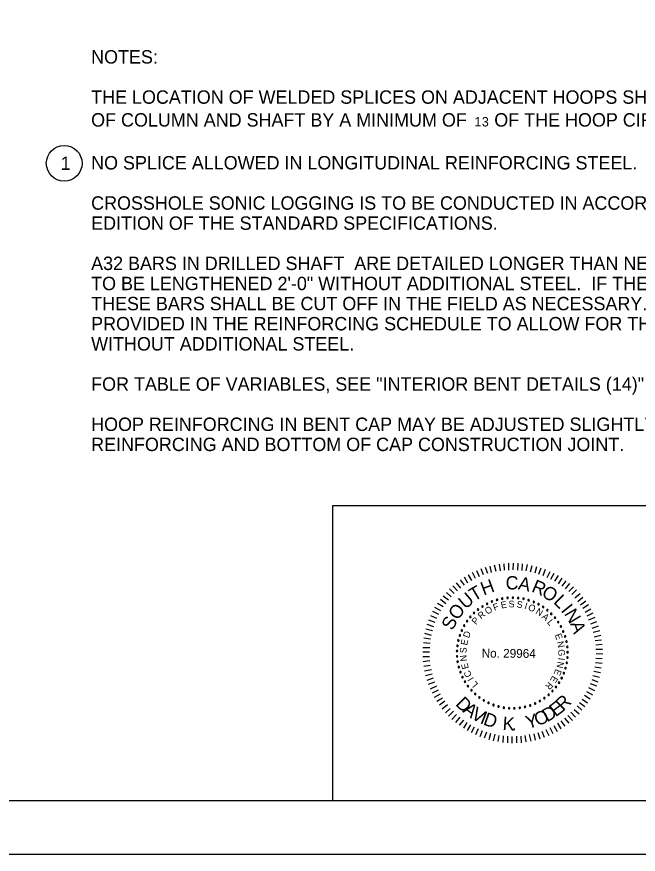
# Model space of a CAD drawing. Extents: x -225.1 to -152.9, y -16.8 to 27.2.
# Drawn here: x -185.7 to -174.12, y -16.78 to -1.16 of the extents above; entities that cross this region are included whole.
import ezdxf

# ---------------------------------------------------------------- set-up
doc = ezdxf.new("R2010")
doc.units = 0
for name, color, linetype in [('BR_AUTO DIMENSION', 7, 'Continuous'), ('BR_BORDER LINES', 7, 'Continuous'), ('BR_TEXT', 7, 'Continuous'), ('Level 31', 7, 'Continuous')]:
    doc.layers.add(name, color=color, linetype=linetype)

msp = doc.modelspace()

# ---------------------------------------------------------------- linework, layer by layer
at = {"layer": 'BR_AUTO DIMENSION'}
msp.add_circle((-184.815, -3.895), 0.333, dxfattribs=at)
at = {"layer": 'BR_BORDER LINES'}
for p, q in [((-179.809, -10.276), (-169.079, -10.276)), ((-179.809, -15.776), (-179.809, -10.276)), ((-221.411, -15.776), (-154.078, -15.776))]:
    msp.add_line(p, q, dxfattribs=at)
at = {"layer": 'BR_TEXT'}
for p, q in [((-176.765, -11.505), (-176.793, -11.386)), ((-176.686, -11.49), (-176.704, -11.368)), ((-176.607, -11.482), (-176.615, -11.36)), ((-176.528, -11.477), (-176.527, -11.349)), ((-176.444, -11.473), (-176.443, -11.349)), ((-176.36, -11.479), (-176.355, -11.35)), ((-176.279, -11.485), (-176.27, -11.363)), ((-176.202, -11.494), (-176.18, -11.372)), ((-176.121, -11.51), (-176.093, -11.392)), ((-177.151, -11.637), (-177.203, -11.525)), ((-177.077, -11.603), (-177.124, -11.491)), ((-176.999, -11.57), (-177.041, -11.453)), ((-176.92, -11.545), (-176.964, -11.429)), ((-176.848, -11.525), (-176.874, -11.403)), ((-176.039, -11.531), (-176.007, -11.41)), ((-175.966, -11.552), (-175.922, -11.438)), ((-175.887, -11.579), (-175.843, -11.463)), ((-175.815, -11.614), (-175.759, -11.503)), ((-175.743, -11.649), (-175.681, -11.538)), ((-177.352, -11.762), (-177.431, -11.661)), ((-177.29, -11.72), (-177.351, -11.611)), ((-177.22, -11.673), (-177.28, -11.564)), ((-175.668, -11.685), (-175.604, -11.578)), ((-175.602, -11.734), (-175.534, -11.626)), ((-175.535, -11.777), (-175.462, -11.677)), ((-177.544, -11.917), (-177.633, -11.829)), ((-177.486, -11.863), (-177.569, -11.773)), ((-177.42, -11.813), (-177.5, -11.713)), ((-175.47, -11.829), (-175.389, -11.731)), ((-175.407, -11.88), (-175.321, -11.791)), ((-175.351, -11.935), (-175.264, -11.848)), ((-177.653, -12.041), (-177.752, -11.963)), ((-177.603, -11.978), (-177.69, -11.894)), ((-175.295, -11.997), (-175.2, -11.914)), ((-175.24, -12.061), (-175.147, -11.985)), ((-177.798, -12.239), (-177.905, -12.175)), ((-177.749, -12.166), (-177.856, -12.1)), ((-177.705, -12.108), (-177.804, -12.028)), ((-175.193, -12.129), (-175.094, -12.051)), ((-175.149, -12.187), (-175.044, -12.123)), ((-177.867, -12.381), (-177.982, -12.33)), ((-177.832, -12.308), (-177.945, -12.252)), ((-175.105, -12.262), (-174.998, -12.199)), ((-175.069, -12.331), (-174.954, -12.277)), ((-177.902, -12.458), (-178.019, -12.414)), ((-175.034, -12.405), (-174.92, -12.356)), ((-175, -12.482), (-174.886, -12.44)), ((-177.952, -12.611), (-178.073, -12.58)), ((-177.927, -12.539), (-178.05, -12.493)), ((-174.973, -12.563), (-174.858, -12.519)), ((-174.953, -12.635), (-174.833, -12.607)), ((-177.987, -12.766), (-178.109, -12.75)), ((-177.966, -12.695), (-178.091, -12.663)), ((-174.937, -12.72), (-174.816, -12.69)), ((-174.92, -12.792), (-174.802, -12.777)), ((-178.002, -12.928), (-178.131, -12.927)), ((-177.997, -12.849), (-178.12, -12.834)), ((-174.907, -12.874), (-174.785, -12.862)), ((-174.904, -12.953), (-174.784, -12.954)), ((-178.006, -13.01), (-178.132, -13.009)), ((-178.004, -13.096), (-178.132, -13.098)), ((-174.9, -13.036), (-174.778, -13.037)), ((-177.999, -13.173), (-178.123, -13.188)), ((-177.991, -13.256), (-178.113, -13.273)), ((-174.91, -13.199), (-174.788, -13.215)), ((-174.906, -13.121), (-174.786, -13.126)), ((-177.971, -13.335), (-178.097, -13.361)), ((-177.958, -13.419), (-178.08, -13.447)), ((-174.942, -13.36), (-174.822, -13.388)), ((-174.924, -13.281), (-174.806, -13.301)), ((-177.935, -13.493), (-178.059, -13.535)), ((-177.912, -13.57), (-178.029, -13.612)), ((-174.981, -13.517), (-174.867, -13.561)), ((-174.96, -13.444), (-174.84, -13.474)), ((-177.878, -13.644), (-177.993, -13.698)), ((-177.844, -13.717), (-177.958, -13.776)), ((-175.081, -13.74), (-174.966, -13.801)), ((-175.044, -13.668), (-174.931, -13.724)), ((-175.009, -13.594), (-174.896, -13.638)), ((-177.81, -13.791), (-177.919, -13.853)), ((-177.763, -13.865), (-177.872, -13.928)), ((-175.163, -13.887), (-175.059, -13.951)), ((-175.118, -13.813), (-175.012, -13.877)), ((-177.72, -13.924), (-177.821, -13.997)), ((-177.67, -13.991), (-177.77, -14.069)), ((-175.256, -14.011), (-175.164, -14.091)), ((-175.208, -13.945), (-175.111, -14.019)), ((-177.62, -14.058), (-177.709, -14.14)), ((-177.562, -14.11), (-177.652, -14.201)), ((-177.505, -14.171), (-177.589, -14.263)), ((-175.426, -14.188), (-175.341, -14.282)), ((-175.369, -14.129), (-175.284, -14.22)), ((-175.312, -14.078), (-175.218, -14.161)), ((-177.44, -14.223), (-177.521, -14.317)), ((-177.373, -14.275), (-177.453, -14.37)), ((-177.312, -14.318), (-177.374, -14.423)), ((-177.242, -14.364), (-177.304, -14.471)), ((-175.623, -14.332), (-175.557, -14.438)), ((-175.556, -14.29), (-175.484, -14.387)), ((-175.49, -14.239), (-175.41, -14.334)), ((-177.173, -14.404), (-177.228, -14.515)), ((-177.1, -14.439), (-177.149, -14.55)), ((-177.023, -14.474), (-177.067, -14.587)), ((-176.944, -14.498), (-176.99, -14.615)), ((-175.99, -14.506), (-175.948, -14.623)), ((-175.911, -14.483), (-175.869, -14.596)), ((-175.839, -14.449), (-175.785, -14.561)), ((-175.766, -14.415), (-175.705, -14.527)), ((-175.69, -14.376), (-175.628, -14.485)), ((-176.872, -14.523), (-176.901, -14.641)), ((-176.79, -14.537), (-176.82, -14.661)), ((-176.711, -14.56), (-176.731, -14.677)), ((-176.632, -14.569), (-176.642, -14.693)), ((-176.554, -14.575), (-176.555, -14.699)), ((-176.47, -14.581), (-176.471, -14.703)), ((-176.385, -14.577), (-176.383, -14.7)), ((-176.305, -14.572), (-176.297, -14.696)), ((-176.227, -14.564), (-176.208, -14.681)), ((-176.147, -14.543), (-176.12, -14.666)), ((-176.064, -14.53), (-176.034, -14.648))]:
    msp.add_line(p, q, dxfattribs=at)
for centre, start, end in [((-176.748, -12.033), 16.1422, 196.1422), ((-176.651, -12.01), 10.6038, 190.6038), ((-176.651, -12.01), 190.6038, 10.6038), ((-176.552, -11.997), 5.0653, 185.0653), ((-176.552, -11.997), 185.0653, 5.0653), ((-176.452, -11.993), 359.5268, 179.5268), ((-176.452, -11.993), 179.5268, 359.5268), ((-176.353, -11.999), 353.9884, 173.9884), ((-176.353, -11.999), 173.9884, 353.9884), ((-176.254, -12.014), 168.4499, 348.4499), ((-176.254, -12.014), 348.4499, 168.4499), ((-177.019, -12.156), 32.7576, 212.7576), ((-177.019, -12.156), 212.7576, 32.7576), ((-176.933, -12.106), 27.2191, 207.2191), ((-176.933, -12.106), 207.2191, 27.2191), ((-176.842, -12.065), 21.6807, 201.6807), ((-176.842, -12.065), 201.6807, 21.6807), ((-176.748, -12.033), 196.1422, 16.1422), ((-176.158, -12.039), 162.9114, 342.9114), ((-176.158, -12.039), 342.9114, 162.9114), ((-176.064, -12.073), 157.373, 337.373), ((-176.064, -12.073), 337.373, 157.373), ((-175.974, -12.116), 151.8345, 331.8345), ((-175.974, -12.116), 331.8345, 151.8345), ((-175.889, -12.167), 146.2961, 326.2961), ((-175.889, -12.167), 326.2961, 146.2961), ((-177.176, -12.279), 43.8345, 223.8345), ((-177.176, -12.279), 223.8345, 43.8345), ((-177.101, -12.214), 38.2961, 218.2961), ((-177.101, -12.214), 218.2961, 38.2961), ((-175.809, -12.227), 140.7576, 320.7576), ((-175.809, -12.227), 320.7576, 140.7576), ((-175.735, -12.294), 135.2191, 315.2191), ((-175.735, -12.294), 315.2191, 135.2191), ((-177.306, -12.43), 54.9114, 234.9114), ((-177.306, -12.43), 234.9114, 54.9114), ((-177.244, -12.351), 49.373, 229.373), ((-177.244, -12.351), 229.373, 49.373), ((-175.668, -12.367), 129.6807, 309.6807), ((-175.668, -12.367), 309.6807, 129.6807), ((-175.608, -12.447), 124.1422, 304.1422), ((-175.608, -12.447), 304.1422, 124.1422), ((-177.404, -12.603), 65.9884, 245.9884), ((-177.404, -12.603), 245.9884, 65.9884), ((-177.359, -12.514), 60.4499, 240.4499), ((-177.359, -12.514), 240.4499, 60.4499), ((-175.557, -12.532), 118.6038, 298.6038), ((-175.557, -12.532), 298.6038, 118.6038), ((-175.513, -12.622), 113.0653, 293.0653), ((-175.513, -12.622), 293.0653, 113.0653), ((-177.468, -12.791), 77.0653, 257.0653), ((-177.468, -12.791), 257.0653, 77.0653), ((-177.441, -12.695), 71.5268, 251.5268), ((-177.441, -12.695), 251.5268, 71.5268), ((-175.479, -12.716), 107.5268, 287.5268), ((-175.479, -12.716), 287.5268, 107.5268), ((-175.454, -12.812), 101.9884, 281.9884), ((-175.454, -12.812), 281.9884, 101.9884), ((-177.486, -12.889), 82.6038, 262.6038), ((-177.486, -12.889), 262.6038, 82.6038), ((-175.438, -12.91), 96.4499, 276.4499), ((-175.438, -12.91), 276.4499, 96.4499), ((-177.494, -12.989), 88.1422, 268.1422), ((-177.492, -13.088), 93.6807, 273.6807), ((-177.494, -12.989), 268.1422, 88.1422), ((-177.492, -13.088), 273.6807, 93.6807), ((-175.435, -13.109), 85.373, 265.373), ((-175.432, -13.01), 90.9114, 270.9114), ((-175.435, -13.109), 265.373, 85.373), ((-175.432, -13.01), 270.9114, 90.9114), ((-177.481, -13.187), 99.2191, 279.2191), ((-177.481, -13.187), 279.2191, 99.2191), ((-177.461, -13.285), 104.7576, 284.7576), ((-177.461, -13.285), 284.7576, 104.7576), ((-175.448, -13.208), 79.8345, 259.8345), ((-175.448, -13.208), 259.8345, 79.8345), ((-177.431, -13.38), 110.2961, 290.2961), ((-177.431, -13.38), 290.2961, 110.2961), ((-175.502, -13.4), 68.7576, 248.7576), ((-175.502, -13.4), 248.7576, 68.7576), ((-175.471, -13.305), 74.2961, 254.2961), ((-175.471, -13.305), 254.2961, 74.2961), ((-177.392, -13.472), 115.8345, 295.8345), ((-177.392, -13.472), 295.8345, 115.8345), ((-177.345, -13.559), 121.373, 301.373), ((-177.345, -13.559), 301.373, 121.373), ((-175.592, -13.577), 57.6807, 237.6807), ((-175.592, -13.577), 237.6807, 57.6807), ((-175.543, -13.491), 63.2191, 243.2191), ((-175.543, -13.491), 243.2191, 63.2191), ((-177.289, -13.642), 126.9114, 306.9114), ((-177.289, -13.642), 306.9114, 126.9114), ((-177.225, -13.719), 132.4499, 312.4499), ((-177.225, -13.719), 312.4499, 132.4499), ((-175.715, -13.734), 46.6038, 226.6038), ((-175.715, -13.734), 226.6038, 46.6038), ((-175.65, -13.659), 52.1422, 232.1422), ((-175.65, -13.659), 232.1422, 52.1422), ((-177.155, -13.789), 137.9884, 317.9884), ((-177.155, -13.789), 317.9884, 137.9884), ((-177.078, -13.852), 143.5268, 323.5268), ((-177.078, -13.852), 323.5268, 143.5268), ((-176.995, -13.908), 329.0653, 149.0653), ((-175.865, -13.865), 35.5268, 215.5268), ((-175.865, -13.865), 215.5268, 35.5268), ((-175.787, -13.803), 41.0653, 221.0653), ((-175.787, -13.803), 221.0653, 41.0653), ((-176.995, -13.908), 149.0653, 329.0653), ((-176.907, -13.955), 154.6038, 334.6038), ((-176.907, -13.955), 334.6038, 154.6038), ((-176.815, -13.994), 160.1422, 340.1422), ((-176.815, -13.994), 340.1422, 160.1422), ((-176.72, -14.023), 345.6807, 165.6807), ((-176.72, -14.023), 165.6807, 345.6807), ((-176.622, -14.043), 351.2191, 171.2191), ((-176.622, -14.043), 171.2191, 351.2191), ((-176.523, -14.054), 356.7576, 176.7576), ((-176.424, -14.055), 2.2961, 182.2961), ((-176.324, -14.046), 7.8345, 187.8345), ((-176.324, -14.046), 187.8345, 7.8345), ((-176.226, -14.028), 13.373, 193.373), ((-176.226, -14.028), 193.373, 13.373), ((-176.131, -14.001), 18.9114, 198.9114), ((-176.131, -14.001), 198.9114, 18.9114), ((-176.038, -13.964), 24.4499, 204.4499), ((-176.038, -13.964), 204.4499, 24.4499), ((-175.949, -13.919), 29.9884, 209.9884), ((-175.949, -13.919), 209.9884, 29.9884), ((-176.523, -14.054), 176.7576, 356.7576), ((-176.424, -14.055), 182.2961, 2.2961)]:
    msp.add_arc(centre, 0.014, start, end, dxfattribs=at)
at = {"layer": 'Level 31'}
msp.add_lwpolyline([(-225.077, -16.776), (-153.077, -16.776), (-153.077, 27.224), (-225.077, 27.224)], close=True, dxfattribs=at)

# ---------------------------------------------------------------- texts
at = {"layer": 'BR_TEXT'}
for s, height, p in [('NOTES:', 0.25, (-184.313, -2.035)), ('THE LOCATION OF WELDED SPLICES ON ADJACENT HOOPS SHALL BE STAGGERED AROUND PERIMETER', 0.25, (-184.313, -2.785)), ('OF COLUMN AND SHAFT BY A MINIMUM OF ', 0.25, (-184.313, -3.21)), (' OF THE HOOP CIRCUMFERENCE.', 0.25, (-176.892, -3.21)), ('1', 0.175, (-177.17, -3.208)), ('3', 0.175, (-177.031, -3.208)), ('1', 0.25, (-184.881, -4.018)), ('NO SPLICE ALLOWED IN LONGITUDINAL REINFORCING STEEL.', 0.25, (-184.313, -4.01)), ('CROSSHOLE SONIC LOGGING IS TO BE CONDUCTED IN ACCORDANCE WITH SECTION 727 OF THE 2007 ', 0.25, (-184.313, -4.76)), ('EDITION OF THE STANDARD SPECIFICATIONS.', 0.25, (-184.313, -5.135)), ('A32 BARS IN DRILLED SHAFT  ARE DETAILED LONGER THAN NECESSARY TO ALLOW FOR THE DRILLED SHAFT ', 0.25, (-184.313, -5.885)), ('TO BE LENGTHENED 2\'-0" WITHOUT ADDITIONAL STEEL.  IF THE DRILLED SHAFTS ARE NOT LENGTHENED, ', 0.25, (-184.313, -6.26)), ('THESE BARS SHALL BE CUT OFF IN THE FIELD AS NECESSARY.  3 ADDITIONAL TA2250 FOR EACH SHAFT ARE ', 0.25, (-184.313, -6.635)), ('PROVIDED IN THE REINFORCING SCHEDULE TO ALLOW FOR THE DRILLED SHAFTS TO BE LENGTHENED 2\'-0" ', 0.25, (-184.313, -7.01)), ('WITHOUT ADDITIONAL STEEL.', 0.25, (-184.313, -7.385)), ('FOR TABLE OF VARIABLES, SEE "INTERIOR BENT DETAILS (14)" SHEET.', 0.25, (-184.313, -8.135)), ('HOOP REINFORCING IN BENT CAP MAY BE ADJUSTED SLIGHTLY TO AVOID CONFLICT WITH BENT CAP', 0.25, (-184.313, -8.885)), ('REINFORCING AND BOTTOM OF CAP CONSTRUCTION JOINT.', 0.25, (-184.313, -9.26))]:
    msp.add_text(s, height=height, dxfattribs=at).set_placement(p)
for s, height, rotation, p in [('H', 0.248, 20.3637, (-176.998, -11.954)), ('C', 0.248, 359.5482, (-176.589, -11.838)), ('A', 0.248, 348.1981, (-176.367, -11.836)), ('R', 0.248, 337.4344, (-176.12, -11.876)), ('T', 0.248, 30.4992, (-177.174, -12.069)), ('O', 0.248, 326.5869, (-175.936, -11.949)), ('U', 0.248, 40.8022, (-177.336, -12.219)), ('L', 0.248, 315.9488, (-175.71, -12.085)), ('O', 0.248, 52.0267, (-177.485, -12.427)), ('O', 0.124, 30.8477, (-176.93, -12.312)), ('F', 0.124, 20.6127, (-176.796, -12.24)), ('E', 0.124, 11.4103, (-176.665, -12.197)), ('S', 0.124, 2.208, (-176.53, -12.175)), ('S', 0.124, 352.6608, (-176.387, -12.175)), ('I', 0.124, 343.1136, (-176.247, -12.199)), ('O', 0.124, 338.4392, (-176.18, -12.219)), ('I', 0.248, 308.6613, (-175.568, -12.234)), ('R', 0.124, 40.3949, (-177.043, -12.4)), ('N', 0.124, 328.2042, (-176.041, -12.282)), ('A', 0.124, 318.657, (-175.923, -12.362)), ('N', 0.248, 300.7037, (-175.506, -12.292)), ('S', 0.248, 63.2511, (-177.576, -12.618)), ('P', 0.124, 49.9421, (-177.139, -12.505)), ('L', 0.124, 309.4546, (-175.823, -12.457)), ('A', 0.248, 289.4792, (-175.388, -12.478)), ('D', 0.124, 69.0364, (-177.273, -12.756)), ('E', 0.124, 78.2388, (-177.306, -12.889)), ('E', 0.124, 291.049, (-175.675, -12.688)), ('S', 0.124, 87.786, (-177.317, -13.031)), ('No. 29964', 0.1635, 359.5268, (-177.035, -13.108)), ('N', 0.124, 281.8466, (-175.631, -12.818)), ('N', 0.124, 97.3332, (-177.305, -13.173)), ('G', 0.124, 272.2995, (-175.608, -12.958)), ('E', 0.124, 106.5355, (-177.271, -13.306)), ('N', 0.124, 257.7339, (-175.617, -13.175)), ('I', 0.124, 262.4084, (-175.608, -13.106)), ('C', 0.124, 116.4266, (-177.211, -13.441)), ('E', 0.124, 248.1867, (-175.653, -13.313)), ('I', 0.124, 121.1011, (-177.175, -13.501)), ('L', 0.124, 129.9595, (-177.094, -13.605)), ('R', 0.124, 229.782, (-175.785, -13.553)), ('E', 0.124, 238.9844, (-175.709, -13.439)), ('D', 0.247, 315.4053, (-177.535, -13.987)), ('R', 0.247, 44.5947, (-175.513, -14.118)), ('A', 0.247, 322.8377, (-177.402, -14.118)), ('V', 0.247, 330.5179, (-177.247, -14.234)), ('D', 0.247, 30.1015, (-175.816, -14.319)), ('E', 0.247, 37.5339, (-175.654, -14.225)), ('I', 0.247, 338.1981, (-177.079, -14.329)), ('D', 0.247, 340.7995, (-177.019, -14.356)), ('Y', 0.247, 14.8649, (-176.178, -14.442)), ('O', 0.247, 22.4212, (-175.995, -14.393)), ('K', 0.247, 356.098, (-176.649, -14.457)), ('.', 0.247, 3.1588, (-176.471, -14.47))]:
    msp.add_text(s, height=height, rotation=rotation, dxfattribs=at).set_placement(p)

doc.saveas('drawing.dxf')
